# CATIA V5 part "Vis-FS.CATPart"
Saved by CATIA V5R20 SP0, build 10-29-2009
Part number: Vis FS M12x35
Bounding box of the stored display mesh (mm): x -10.897 to 10.897, y -10.885 to 10.885, z 0 to 35
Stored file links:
  C:\travail\CAO\bib catia\vis\Vis-FS.CATPart
  C:\Program Files\Dassault Systemes\B20\win_b64\reffiles\standard\MetricThickPitch.txt
  C:\travail\CAO\bib catia\vis\vis-FS.xls
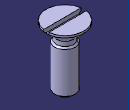
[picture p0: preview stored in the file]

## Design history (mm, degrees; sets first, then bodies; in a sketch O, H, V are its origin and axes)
Parameters
  Designation = "Vis FS M12x35" {design table}
  Filetage = "M12" {design table}
  D = 12 mm {design table}
  Dk = 22 mm {design table}
  L = 35 mm {design table}
  Ds = 10.2 mm {design table}
  a = 3.5 mm {design table}
  t = 2.4 mm {design table}
  n = 3 mm {design table}
Body1 (main body)
  Sketch1 on yz-plane, origin (0, 0, 0), H (0, 1, 0), V (0, 0, 1)
    axis line L1 (0, 0) -> (0, 12.878)
    line L2 (0, 0) -> (-6, 0)
    line L3 (-6, 0) -> (-6, 24.4)
    point P3 (-6, 24.4)
    line L4 (-6, 24.4) -> (-5.1, 25.3)
    line L5 (-5.1, 25.3) -> (-5.1, 27.9)
    point P5 (-5.1, 27.9)
    line L6 (-5.1, 27.9) -> (-11, 33.8)
    line L7 (-11, 33.8) -> (-11, 35)
    line L8 (-11, 35) -> (0, 35)
    point P8 (0, 35)
    line L9 (0, 35) -> (0, 0)
    "Radius" L1 L3 = 6 {= D /2}
    length L7 = 1.2 {= Sketch1.Radius(L1 L3) /5}
    angle L6 L1 = 45
    "Radius" L1 L5 = 5.1 {= Ds /2}
    angle L3 L4 = 45
    distance L8 L2 = 35 {= L}
    distance P3 P5 V = 3.5 {= a}
    "Radius" L7 L1 = 11 {= Dk /2}
    vertical: L1 V, L3 V, L5 V, L7 V, L9 V
    horizontal: L2 H, L8 H
    coincidence: P8 L1
  Shaft1: profile Sketch1, axis Sketch1.L1, angle 360
  Thread1: "M12", diameter 12, depth 24.4, pitch 1.75, on face of Shaft1 from Sketch1.L3, from face of Shaft1 from Sketch1.L2
  Chamfer1: length 0.875 {= Thread1.Pitch /2}, angle 45, on edge [face of Shaft1 from Sketch1.L2 | face of Shaft1 from Sketch1.L3]
  Sketch2 on yz-plane, origin (0, 0, 0), H (0, 1, 0), V (0, 0, 1)
    axis line L1 (0, 0) -> (0, 13.1188)
    line L2 (-1.5, 35) -> (1.5, 35)
    line L3 (1.5, 35) -> (1.5, 32.6)
    line L4 (1.5, 32.6) -> (-1.5, 32.6)
    line L5 (-1.5, 32.6) -> (-1.5, 35)
    reference projected line E1 (-4.65, 35) -> (4.65, 35) from edge [face of Shaft1 from Sketch1.L7 | face of Shaft1 from Sketch1.L8]
    length L2 = 3 {= n}
    length L3 = 2.4 {= t}
    vertical: L1 V, L3 V, L5 V
    horizontal: L2 H, L4 H
    symmetry: L3 L5 L1
    coincidence: L2 E1
  Pocket1: profile Sketch2, direction (-1, 0, 0), through (limit type 6), opposite side through (limit type 6)
Relations
  Thread1.ThreadDescription = Filetage
  design table, configuration 8, drives D, Dk, L, Ds, a, n, t, Filetage, Designation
